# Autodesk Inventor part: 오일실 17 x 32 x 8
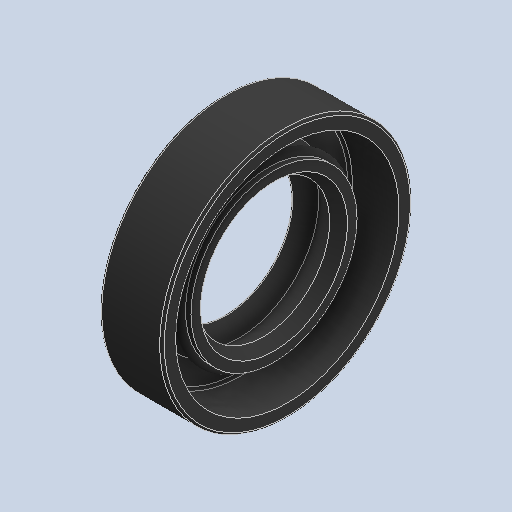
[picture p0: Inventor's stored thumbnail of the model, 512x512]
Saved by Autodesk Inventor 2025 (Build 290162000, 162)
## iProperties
Created: 2024-07
Part Number: 오일실 17 x 32 x 8
Material: 고무
Description: 오일-실
Document SubType Name: Modeling
Designer: 학생
Density: 0.93 g/cm^3
Appearance: 기본값
Author: jhkim
Sending System: Autodesk Inventor 2025
Preprocessor: ST-DEVELOPER v20
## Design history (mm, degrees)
feature "Solid1"
node "솔리드1"
